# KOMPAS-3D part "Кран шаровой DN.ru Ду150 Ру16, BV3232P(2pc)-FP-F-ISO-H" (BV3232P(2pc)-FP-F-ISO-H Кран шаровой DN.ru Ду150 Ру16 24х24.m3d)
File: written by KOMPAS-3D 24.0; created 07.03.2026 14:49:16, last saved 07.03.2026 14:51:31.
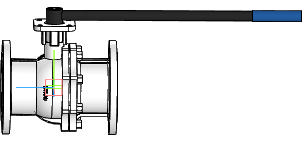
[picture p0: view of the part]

Document properties: Автор: R2D2; Полное имя файла: E:\Работа\Зайцев\BV3232P(2pc)-FP-F-ISO-H Кран шаровой DN.ru Ду15-300 Ру16-40\DN150 PN16 24х24\исходные материалы\BV3232P(2pc)-FP-F-ISO-H Кран шаровой DN.ru Ду150 Ру16 24х24.m3d

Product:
- Part/product: Кран шаровой DN.ru Ду150 Ру16  | designation BV3232P(2pc)-FP-F-ISO-H
    Масса: 41
    Раздел спецификации: Прочие изделия
    Примечание: D160-77516

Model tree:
1. Операция без истории:2

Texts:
  BV3232P(2pc)-FP-F-ISO-H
